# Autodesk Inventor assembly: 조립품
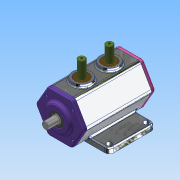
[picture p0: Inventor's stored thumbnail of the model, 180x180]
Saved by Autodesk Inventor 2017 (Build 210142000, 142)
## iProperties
Part Number: 조립품
Material: 일반
Document SubType Name: Assembly
Designer: user
Author: user
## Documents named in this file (11)
- C:\Users\user\Desktop\710606V1043\조립품.iam
- C:\Users\user\Desktop\710606V1043\본체.ipt
- C:\Users\user\Desktop\710606V1043\볼트 M4.ipt
- C:\Users\user\Desktop\710606V1043\부시.ipt
- C:\Users\user\Desktop\710606V1043\슬라이더.ipt
- C:\Users\user\Desktop\710606V1043\앞커버.ipt
- C:\Users\user\Desktop\710606V1043\오일실.ipt
- C:\Users\user\Desktop\710606V1043\편심축.ipt
- C:\Users\user\Desktop\710606V1043\뒷커버.ipt
- C:\Users\user\Desktop\710606V1043\베어링 6203.ipt
- C:\Users\user\Desktop\710606V1043\베어링 6302.ipt
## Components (10 placed, 3 different names)
1. 8-오일실:1
2. 7-베어링 6203:1
3. 9-M4-소켓머리:2
4. 9-M4-소켓머리:3
5. 9-M4-소켓머리:4
6. 9-M4-소켓머리:5
7. 9-M4-소켓머리:1
8. 9-M4-소켓머리:6
9. 9-M4-소켓머리:7
10. 9-M4-소켓머리:8
